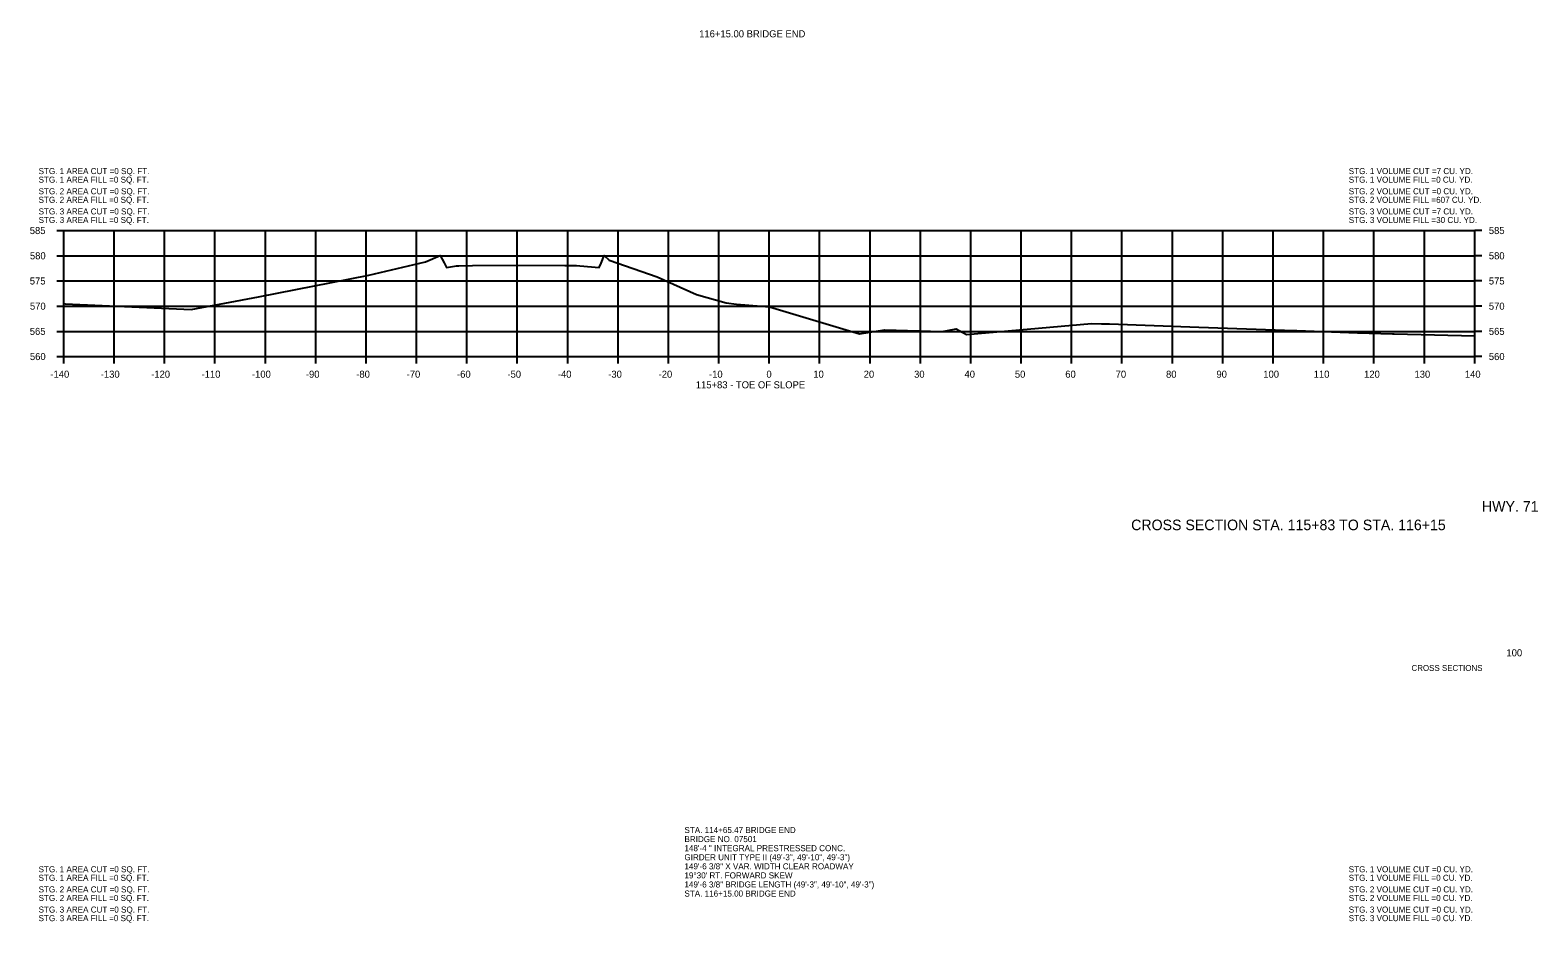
# Model space of a CAD drawing. Extents: x 642114 to 642416, y 286928 to 293347.
# Drawn here: x 642113.6 to 642412.8, y 289960.3 to 290137.4 of the extents above; entities that cross this region are included whole.
import ezdxf

# ---------------------------------------------------------------- set-up
doc = ezdxf.new("R2010")
doc.units = 0
for name, color, linetype in [('R_Axis', 7, 'Continuous'), ('R_Axis Annot', 7, 'Continuous'), ('R_Border', 7, 'Continuous'), ('R_Border Notes', 7, 'Continuous'), ('R_Draft', 7, 'Continuous'), ('R_Exist Surface', 7, 'Continuous'), ('R_Grid', 7, 'Continuous')]:
    doc.layers.add(name, color=color, linetype=linetype)

msp = doc.modelspace()

# ---------------------------------------------------------------- linework, layer by layer
at = {"layer": 'R_Axis'}
for p, q in [((642118.84, 290097.66), (642120.24, 290097.66)), ((642120.24, 290072.66), (642120.24, 290097.66)), ((642400.24, 290072.66), (642400.24, 290097.66)), ((642401.64, 290097.66), (642400.24, 290097.66)), ((642118.84, 290092.66), (642120.24, 290092.66)), ((642401.64, 290092.66), (642400.24, 290092.66)), ((642118.84, 290087.66), (642120.24, 290087.66)), ((642401.64, 290087.66), (642400.24, 290087.66)), ((642118.84, 290082.66), (642120.24, 290082.66)), ((642401.64, 290082.66), (642400.24, 290082.66)), ((642118.84, 290077.66), (642120.24, 290077.66)), ((642401.64, 290077.66), (642400.24, 290077.66)), ((642118.84, 290072.66), (642120.24, 290072.66)), ((642120.24, 290072.66), (642400.24, 290072.66)), ((642120.24, 290071.26), (642120.24, 290072.66)), ((642130.24, 290071.26), (642130.24, 290072.66)), ((642140.24, 290071.26), (642140.24, 290072.66)), ((642150.24, 290071.26), (642150.24, 290072.66)), ((642160.24, 290071.26), (642160.24, 290072.66)), ((642170.24, 290071.26), (642170.24, 290072.66)), ((642180.24, 290071.26), (642180.24, 290072.66)), ((642190.24, 290071.26), (642190.24, 290072.66)), ((642200.24, 290071.26), (642200.24, 290072.66)), ((642210.24, 290071.26), (642210.24, 290072.66)), ((642220.24, 290071.26), (642220.24, 290072.66)), ((642230.24, 290071.26), (642230.24, 290072.66)), ((642240.24, 290071.26), (642240.24, 290072.66)), ((642250.24, 290071.26), (642250.24, 290072.66)), ((642260.24, 290071.26), (642260.24, 290072.66)), ((642270.24, 290071.26), (642270.24, 290072.66)), ((642280.24, 290071.26), (642280.24, 290072.66)), ((642290.24, 290071.26), (642290.24, 290072.66)), ((642300.24, 290071.26), (642300.24, 290072.66)), ((642310.24, 290071.26), (642310.24, 290072.66)), ((642320.24, 290071.26), (642320.24, 290072.66)), ((642330.24, 290071.26), (642330.24, 290072.66)), ((642340.24, 290071.26), (642340.24, 290072.66)), ((642350.24, 290071.26), (642350.24, 290072.66)), ((642360.24, 290071.26), (642360.24, 290072.66)), ((642370.24, 290071.26), (642370.24, 290072.66)), ((642380.24, 290071.26), (642380.24, 290072.66)), ((642390.24, 290071.26), (642390.24, 290072.66)), ((642400.24, 290071.26), (642400.24, 290072.66)), ((642401.64, 290072.66), (642400.24, 290072.66))]:
    msp.add_line(p, q, dxfattribs=at)
at = {"layer": 'R_Exist Surface'}
msp.add_lwpolyline([(642120.24, 290083.16), (642120.53, 290083.15), (642145.51, 290082), (642158.85, 290084.52), (642180.8, 290088.82), (642192.01, 290091.48), (642194.95, 290092.7), (642195.74, 290091.23), (642196.18, 290090.36), (642198.18, 290090.63), (642198.66, 290090.69), (642201.33, 290090.71), (642210.03, 290090.8), (642219.65, 290090.72), (642221.99, 290090.7), (642222.64, 290090.64), (642226.5, 290090.35), (642226.9, 290091.21), (642227.51, 290092.73), (642228.5, 290091.77), (642237.99, 290088.46), (642245.79, 290084.96), (642251.72, 290083.34), (642253.74, 290083.07), (642260.3, 290082.54), (642278.15, 290077.17), (642283.13, 290077.98), (642294.56, 290077.63), (642297.33, 290078.15), (642299.39, 290077.05), (642324.16, 290079.22), (642326.2, 290079.17), (642327.77, 290079.14), (642345.52, 290078.5), (642364.42, 290077.83), (642364.92, 290077.83), (642376.95, 290077.39), (642383.93, 290077.2), (642384.08, 290077.2), (642384.22, 290077.2), (642400.24, 290076.79)], dxfattribs=at)
at = {"layer": 'R_Grid'}
for p, q in [((642120.24, 290097.66), (642400.24, 290097.66)), ((642120.24, 290072.66), (642120.24, 290097.66)), ((642130.24, 290072.66), (642130.24, 290097.66)), ((642140.24, 290072.66), (642140.24, 290097.66)), ((642150.24, 290072.66), (642150.24, 290097.66)), ((642160.24, 290072.66), (642160.24, 290097.66)), ((642170.24, 290072.66), (642170.24, 290097.66)), ((642180.24, 290072.66), (642180.24, 290097.66)), ((642190.24, 290072.66), (642190.24, 290097.66)), ((642200.24, 290072.66), (642200.24, 290097.66)), ((642210.24, 290072.66), (642210.24, 290097.66)), ((642220.24, 290072.66), (642220.24, 290097.66)), ((642230.24, 290072.66), (642230.24, 290097.66)), ((642240.24, 290072.66), (642240.24, 290097.66)), ((642250.24, 290072.66), (642250.24, 290097.66)), ((642260.24, 290072.66), (642260.24, 290097.66)), ((642270.24, 290072.66), (642270.24, 290097.66)), ((642280.24, 290072.66), (642280.24, 290097.66)), ((642290.24, 290072.66), (642290.24, 290097.66)), ((642300.24, 290072.66), (642300.24, 290097.66)), ((642310.24, 290072.66), (642310.24, 290097.66)), ((642320.24, 290072.66), (642320.24, 290097.66)), ((642330.24, 290072.66), (642330.24, 290097.66)), ((642340.24, 290072.66), (642340.24, 290097.66)), ((642350.24, 290072.66), (642350.24, 290097.66)), ((642360.24, 290072.66), (642360.24, 290097.66)), ((642370.24, 290072.66), (642370.24, 290097.66)), ((642380.24, 290072.66), (642380.24, 290097.66)), ((642390.24, 290072.66), (642390.24, 290097.66)), ((642400.24, 290072.66), (642400.24, 290097.66)), ((642120.24, 290092.66), (642400.24, 290092.66)), ((642120.24, 290087.66), (642400.24, 290087.66)), ((642120.24, 290082.66), (642400.24, 290082.66)), ((642120.24, 290077.66), (642400.24, 290077.66)), ((642120.24, 290072.66), (642400.24, 290072.66))]:
    msp.add_line(p, q, dxfattribs=at)

# ---------------------------------------------------------------- texts
at = {"layer": 'R_Axis Annot'}
for s, height, p in [('116+15.00 BRIDGE END', 1.4, (642246.33, 290136)), ('585', 1.4, (642113.49, 290096.96)), ('585', 1.4, (642403.04, 290096.96)), ('580', 1.4, (642113.52, 290091.96)), ('580', 1.4, (642403.04, 290091.96)), ('575', 1.4, (642113.49, 290086.96)), ('575', 1.4, (642403.04, 290086.96)), ('570', 1.4, (642113.52, 290081.96)), ('570', 1.4, (642403.04, 290081.96)), ('565', 1.4, (642113.49, 290076.96)), ('565', 1.4, (642403.04, 290076.96)), ('560', 1.4, (642113.52, 290071.96)), ('560', 1.4, (642403.04, 290071.96)), ('-140', 1.4, (642117.58, 290068.46)), ('-130', 1.4, (642127.58, 290068.46)), ('-120', 1.4, (642137.58, 290068.46)), ('-110', 1.4, (642147.58, 290068.46)), ('-100', 1.4, (642157.58, 290068.46)), ('-90', 1.4, (642168.28, 290068.46)), ('-80', 1.4, (642178.28, 290068.46)), ('-70', 1.4, (642188.28, 290068.46)), ('-60', 1.4, (642198.28, 290068.46)), ('-50', 1.4, (642208.28, 290068.46)), ('-40', 1.4, (642218.28, 290068.46)), ('-30', 1.4, (642228.28, 290068.46)), ('-20', 1.4, (642238.28, 290068.46)), ('115+83 - TOE OF SLOPE', 1.4, (642245.66, 290066.36)), ('-10', 1.4, (642248.28, 290068.46)), ('0', 1.4, (642259.68, 290068.46)), ('10', 1.4, (642268.98, 290068.46)), ('20', 1.4, (642278.98, 290068.46)), ('30', 1.4, (642288.98, 290068.46)), ('40', 1.4, (642298.98, 290068.46)), ('50', 1.4, (642308.98, 290068.46)), ('60', 1.4, (642318.98, 290068.46)), ('70', 1.4, (642328.98, 290068.46)), ('80', 1.4, (642338.98, 290068.46)), ('90', 1.4, (642348.98, 290068.46)), ('100', 1.4, (642358.28, 290068.46)), ('110', 1.4, (642368.28, 290068.46)), ('120', 1.4, (642378.28, 290068.46)), ('130', 1.4, (642388.28, 290068.46)), ('140', 1.4, (642398.28, 290068.46)), ('HWY. 71', 2.1, (642401.67, 290041.88)), ('CROSS SECTION STA. 115+83 TO STA. 116+15', 2.1, (642332.06, 290038.21))]:
    msp.add_text(s, height=height, dxfattribs=at).set_placement(p)
at = {"layer": 'R_Border'}
msp.add_text('100', height=1.4, dxfattribs=at).set_placement((642406.53, 290013.19))
at = {"layer": 'R_Border Notes'}
msp.add_text('    CROSS SECTIONS    ', height=1.178, dxfattribs=at).set_placement((642385.94, 290010.29))
at = {"layer": 'R_Draft'}
for s, p in [('STG. 1 AREA CUT =0 SQ. FT.', (642115.24, 290108.86)), ('STG. 1 VOLUME CUT =7 CU. YD.', (642375.24, 290108.86)), ('STG. 1 AREA FILL =0 SQ. FT.', (642115.24, 290107.16)), ('STG. 1 VOLUME FILL =0 CU. YD.', (642375.24, 290107.16)), ('STG. 2 AREA CUT =0 SQ. FT.', (642115.24, 290104.86)), ('STG. 2 AREA FILL =0 SQ. FT.', (642115.24, 290103.16)), ('STG. 2 VOLUME CUT =0 CU. YD.', (642375.24, 290104.86)), ('STG. 2 VOLUME FILL =607 CU. YD.', (642375.24, 290103.16)), ('STG. 3 AREA CUT =0 SQ. FT.', (642115.24, 290100.86)), ('STG. 3 VOLUME CUT =7 CU. YD.', (642375.24, 290100.86)), ('STG. 3 AREA FILL =0 SQ. FT.', (642115.24, 290099.16)), ('STG. 3 VOLUME FILL =30 CU. YD.', (642375.24, 290099.16)), ('STG. 1 AREA CUT =0 SQ. FT.', (642115.24, 289970.34)), ('STG. 1 AREA FILL =0 SQ. FT.', (642115.24, 289968.64)), ('STG. 1 VOLUME CUT =0 CU. YD.', (642375.24, 289970.34)), ('STG. 1 VOLUME FILL =0 CU. YD.', (642375.24, 289968.64)), ('STG. 2 AREA CUT =0 SQ. FT.', (642115.24, 289966.34)), ('STG. 2 AREA FILL =0 SQ. FT.', (642115.24, 289964.64)), ('STG. 2 VOLUME CUT =0 CU. YD.', (642375.24, 289966.34)), ('STG. 2 VOLUME FILL =0 CU. YD.', (642375.24, 289964.64)), ('STG. 3 AREA CUT =0 SQ. FT.', (642115.24, 289962.34)), ('STG. 3 VOLUME CUT =0 CU. YD.', (642375.24, 289962.34)), ('STG. 3 AREA FILL =0 SQ. FT.', (642115.24, 289960.64)), ('STG. 3 VOLUME FILL =0 CU. YD.', (642375.24, 289960.64))]:
    msp.add_text(s, height=1.2, dxfattribs=at).set_placement(p)
for s, p in [('STA. 114+65.47 BRIDGE END', (642243.41, 289978.12)), ('148\'-4 " INTEGRAL PRESTRESSED CONC. ', (642243.41, 289974.52)), ('BRIDGE NO. 07501 ', (642243.41, 289976.32)), ('GIRDER UNIT TYPE II (49\'-3", 49\'-10", 49\'-3")', (642243.41, 289972.72)), ('149\'-6 3/8" X VAR. WIDTH CLEAR ROADWAY', (642243.41, 289970.92)), ("19%%d30' RT. FORWARD SKEW", (642243.41, 289969.12)), ('STA. 116+15.00 BRIDGE END', (642243.41, 289965.52)), ('149\'-6 3/8" BRIDGE LENGTH (49\'-3", 49\'-10", 49\'-3")', (642243.41, 289967.32))]:
    msp.add_text(s, height=1.2, rotation=360, dxfattribs=at).set_placement(p)

doc.saveas('drawing.dxf')
